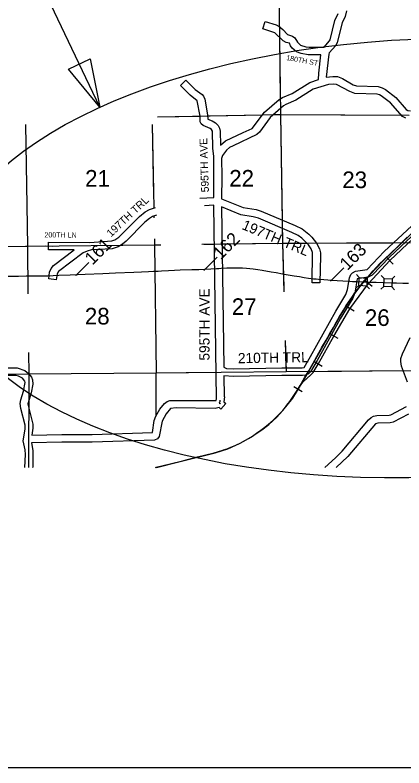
# Model space of a CAD drawing. Extents: x 10133 to 81668, y 5524 to 11018.
# Drawn here: x 14867 to 15247, y 7924 to 8660 of the extents above; entities that cross this region are included whole.
import ezdxf

# ---------------------------------------------------------------- set-up
doc = ezdxf.new("R2010")
doc.units = 0
for name, color, linetype in [('Default', 7, 'Continuous'), ('DisCLMLSUR', 7, 'Continuous'), ('dsnShtPortLev01', 7, 'Continuous'), ('DsnShtRevisedText', 7, 'Continuous'), ('dsnTextFinalPlan', 7, 'Continuous'), ('Level 3', 7, 'Continuous')]:
    doc.layers.add(name, color=color, linetype=linetype)

msp = doc.modelspace()

# ---------------------------------------------------------------- linework, layer by layer
at = {"layer": 'Default'}
for p, q in [((15236.21, 8416.3), (15229.82, 8423.16)), ((15203.2, 8403.09), (15200.58, 8405.99)), ((15215.76, 8394.4), (15208.49, 8400.33)), ((15211.01, 8402.68), (15213.92, 8405.29)), ((15227.32, 8402.23), (15224.66, 8405.09)), ((15235.14, 8401.94), (15238.01, 8404.61)), ((15202.79, 8395.27), (15199.88, 8392.65)), ((15210.61, 8394.86), (15213.22, 8391.95)), ((15227.04, 8394.41), (15224.17, 8391.74)), ((15234.86, 8394.12), (15237.52, 8391.26)), ((15198.05, 8370.2), (15190.06, 8375.11)), ((15182.49, 8343.5), (15174.33, 8348.13)), ((15167, 8316.25), (15158.9, 8320.96)), ((15147.27, 8291.53), (15139.2, 8296.3))]:
    msp.add_line(p, q, dxfattribs=at)
for points in [[(15124.6, 8686.39), (15125.11, 8648.26)], [(15124.6, 8686.39), (15126.27, 8562.47)], [(15047.66, 8480.66), (15061.22, 8481.33), (15061.34, 8521.33), (15060.35, 8529.66), (15059.91, 8545.99), (15059.01, 8547.76), (15057.59, 8548.81), (15050.73, 8551.6), (15048.69, 8553.24), (15047.91, 8555.18), (15047.71, 8560.86), (15044.94, 8575.85), (15038.03, 8581.31), (15028.7, 8590.62), (15033.91, 8596.02), (15042.99, 8586.95), (15049.69, 8581.94), (15051.07, 8580.24), (15052.35, 8577.32), (15055.11, 8562.07), (15055.34, 8557.94), (15059.7, 8556.22), (15062.96, 8554.22), (15065.45, 8551.71), (15066.79, 8549.13), (15067.47, 8546.1), (15067.78, 8532.38), (15072.67, 8536.58), (15089.67, 8544.94), (15098.61, 8548.64), (15110.72, 8564.75), (15124.99, 8577.1), (15128.26, 8579.1), (15137.64, 8582.95), (15154.77, 8593.75), (15163.51, 8596.76), (15163.58, 8602.82), (15165.55, 8620.85), (15153.29, 8620.63), (15146.34, 8621.92), (15141.99, 8623.59), (15137.74, 8627.29), (15136.17, 8629.42), (15135.03, 8632.06), (15131.88, 8632.92), (15128.8, 8634.48), (15120.77, 8642.16), (15109.1, 8645.98), (15111.22, 8653.17), (15121.95, 8649.98), (15125.02, 8648.33), (15128.58, 8645.43), (15133.16, 8640.58), (15137.98, 8639), (15140.37, 8637.48), (15142.76, 8633.05), (15145.72, 8630.11), (15150.83, 8628.5), (15154.11, 8628.08), (15168.79, 8628.15), (15174.08, 8634.25), (15174.66, 8635.51), (15179.26, 8654.2), (15182.39, 8660.98)], [(15190.61, 8663.67), (15189.4, 8658.29), (15186.45, 8652.05), (15181.61, 8632.68), (15180.21, 8629.91), (15173.88, 8622.58), (15173.31, 8621.36), (15170.97, 8598.84), (15177.42, 8599.68), (15181.87, 8599.43), (15186.78, 8597.53), (15197.33, 8591.55), (15200.53, 8590.35), (15221.49, 8589.64), (15225.55, 8588.59), (15228.75, 8586.98), (15238.89, 8579.14), (15249.07, 8567.34), (15250.56, 8566.19), (15253.22, 8565.92)], [(15125.25, 8637.95), (15126.06, 8577.75)], [(15248.46, 8558.98), (15245.39, 8560.55), (15233.73, 8573.68), (15224.46, 8580.82), (15222.74, 8581.63), (15220.75, 8582.17), (15198.92, 8583.02), (15194, 8584.83), (15180.97, 8591.88), (15177.77, 8592.19), (15172.96, 8591.6), (15158.12, 8587.04), (15141.34, 8576.43), (15131.55, 8572.36), (15129.1, 8570.83), (15116.23, 8559.65), (15105.68, 8545.18), (15103.25, 8542.73), (15080.07, 8531.97), (15076.43, 8530.08), (15073.52, 8527.55), (15069.63, 8522.33), (15068.64, 8519.52), (15069.04, 8501.99), (15068.71, 8480.14), (15089.9, 8471.43), (15102.47, 8469.5), (15107.51, 8468.01), (15140.44, 8454.13), (15147.25, 8450.58), (15154.02, 8445.38), (15156.83, 8442.61), (15161.44, 8436.78), (15164.35, 8431.09), (15165.32, 8427.28), (15165.39, 8424.34), (15164.66, 8397.84), (15157.17, 8398.12), (15157.64, 8427.45), (15156.21, 8431.09), (15153.45, 8434.98), (15147.1, 8441.48), (15143.37, 8444.16), (15137.45, 8447.26), (15104.75, 8461.03), (15099.43, 8462.44), (15087.68, 8464.26), (15068.8, 8472.07), (15070.95, 8315.62), (15073.6, 8314.31), (15080.43, 8314.09), (15127.59, 8314.99)], [(15006.1, 8560.14), (15126.27, 8562.47)], [(15055.17, 8561.09), (15108.66, 8562.13)], [(15119.24, 8562.33), (15126.27, 8562.47)], [(15126.19, 8568.37), (15126.27, 8562.47)], [(15126.27, 8562.47), (15127.79, 8459.47)], [(15126.27, 8562.47), (15244.06, 8561.79)], [(15126.27, 8562.47), (15251.87, 8561.74)], [(15126.27, 8562.47), (15128.13, 8436.72)], [(15006.1, 8560.14), (15047.7, 8560.94)], [(14877.47, 8552.72), (14879.25, 8433.82)], [(14877.47, 8552.72), (14879.25, 8433.82)], [(15000.92, 8552.72), (15002.56, 8471.1)], [(15000.92, 8552.72), (15002.32, 8483.36)], [(14860.23, 8314.95), (14869.12, 8315.01), (14876.77, 8312.26), (14880.29, 8309.48), (14883.1, 8305.81), (14884.26, 8303.24), (14884.57, 8299.02), (14882.84, 8290.36), (14879.73, 8279.77), (14880.14, 8276.68), (14884.4, 8260.03), (14884.56, 8255.86), (14883.48, 8249.18), (14912.77, 8249.84), (14942.26, 8249.66), (15001.18, 8251.65), (15002.92, 8263.54), (15004.54, 8267.84), (15008.5, 8274.56), (15012.95, 8280.01), (15015.56, 8281.93), (15018.23, 8282.9), (15020.74, 8283.17), (15063.5, 8283.04), (15063.9, 8284.58), (15061.29, 8473.83), (15052.06, 8473.23)], [(15005.14, 8463.93), (15001.33, 8462.64), (14998.25, 8460.95), (14993.73, 8457.37), (14975.6, 8438.75), (14972.08, 8435.73), (14967.93, 8433.27), (14961.81, 8431.23), (14941.84, 8430.17), (14937.45, 8429.05), (14933.49, 8427.19), (14909.47, 8409.17), (14908.27, 8406.88), (14907.39, 8400.86), (14899.97, 8401.94), (14900.91, 8408.38), (14902.31, 8412.06), (14904.55, 8414.85), (14924.94, 8430.26), (14899.75, 8430.22), (14899.79, 8437.71), (14940.12, 8437.48), (14961.64, 8438.87), (14964.47, 8439.92), (14968.47, 8442.44), (14988.67, 8462.9), (14994.14, 8467.22), (14998.24, 8469.48), (15004.23, 8471.51)], [(15002.72, 8463.16), (15002.76, 8461.48)], [(15005.18, 8217.55), (15026.86, 8223), (15062.64, 8231.92), (15074.79, 8235.92), (15086.88, 8241.21), (15097.24, 8247.05), (15107.94, 8254.21), (15114.85, 8259.61), (15122.73, 8266.69), (15128.59, 8273.25), (15138.37, 8285.43), (15148.35, 8301.97), (15183.72, 8364.44), (15190.28, 8374.88), (15196.95, 8384.94), (15203.97, 8394.34), (15210.49, 8402.42), (15218.89, 8411.8), (15226.84, 8419.94), (15260.86, 8452.53)], [(15127.59, 8314.99), (15147.55, 8314.83), (15149.39, 8315.36), (15155.7, 8325.94), (15180.16, 8370.31), (15190.12, 8386.43), (15191.73, 8391.4), (15193.5, 8402.93), (15194.79, 8406.15), (15196.5, 8407.86), (15199.5, 8409.36), (15210.86, 8411.15), (15227.34, 8428.44), (15254.52, 8453.71)], [(15259.76, 8448.34), (15232.58, 8423.07), (15215.62, 8405.35), (15211.97, 8403.65), (15200.94, 8401.78), (15198.73, 8388.32), (15196.81, 8383.04), (15184.54, 8362.85), (15162.18, 8322.17), (15155.53, 8311.03), (15153.67, 8309.12), (15150.59, 8307.69), (15147.87, 8307.34), (15127.65, 8307.49), (15080.46, 8306.59), (15070.95, 8307.24), (15071.34, 8286.52), (15071.74, 8286.46), (15071.09, 8281.86), (15072.99, 8280.22), (15068.09, 8274.55), (15066.33, 8276.06), (15062.64, 8275.33), (15024.26, 8275.7), (15018.99, 8275.24), (15014.52, 8270.1), (15010.6, 8262.95), (15007.85, 8247.87), (15006.09, 8245.71), (15003.24, 8244.38), (14942.35, 8242.16), (14912.88, 8242.35), (14883.06, 8241.67), (14884.61, 8234.19), (14884.35, 8217.84), (14884.27, 8217.55)], [(15127.91, 8451.28), (15128.13, 8436.72)], [(15003.17, 8441.03), (15003.29, 8435.14)], [(15004.21, 8217.55), (15004.87, 8217.72), (15018.6, 8221.19), (15031.93, 8224.43), (15045.3, 8227.81), (15061.56, 8231.9), (15065.59, 8233.02), (15069.12, 8234.2), (15070.77, 8234.78), (15074.04, 8235.93), (15077.84, 8237.47), (15081.9, 8239.15), (15086.75, 8241.47), (15090.49, 8243.34), (15094.95, 8245.73), (15098.91, 8248.19), (15102.91, 8250.94), (15107.04, 8253.89), (15111.03, 8256.91), (15114.57, 8259.79), (15119, 8263.69), (15122.31, 8266.93), (15124.67, 8269.46), (15127.42, 8272.31), (15130.04, 8275.35), (15132.53, 8278.43), (15135.32, 8282.01), (15138.03, 8285.81), (15139.41, 8287.92), (15140.07, 8288.92), (15142.49, 8292.66), (15145.47, 8297.7), (15149.67, 8305.04), (15153.76, 8312.15), (15159.79, 8322.51), (15163.76, 8329.65), (15165.31, 8332.52), (15166.38, 8334.5), (15170.8, 8342.04), (15174.41, 8348.39), (15177.88, 8354.36), (15180.99, 8359.76), (15183.55, 8364.29), (15186.2, 8368.81), (15187.65, 8371.23), (15190.46, 8375.82), (15192.63, 8378.93), (15195.84, 8383.65), (15198.95, 8388.07), (15201.41, 8391.45), (15203.93, 8394.66), (15206.75, 8398.2), (15210.22, 8402.46), (15214.35, 8407.18), (15216.68, 8409.83), (15219.79, 8413.11), (15223.62, 8417.04), (15226.02, 8419.43), (15228.6, 8422.05), (15232.93, 8426.09), (15241.61, 8434.47), (15249.97, 8442.47)], [(15128.13, 8436.72), (15253.02, 8437.25)], [(15136, 8282.96), (15138.03, 8285.81), (15139.41, 8287.92), (15140.07, 8288.92), (15142.49, 8292.66), (15145.47, 8297.7), (15148.44, 8301.19), (15155.95, 8308.01), (15158.17, 8310.43), (15162.95, 8318.61), (15178.39, 8345.84), (15194.05, 8372.68), (15212.12, 8397.39), (15233, 8419.74), (15255.62, 8441.36)], [(15161.38, 8436.86), (15236.57, 8437.18)], [(14753.71, 8432.47), (14879.25, 8433.82)], [(14810.27, 8433.07), (14879.25, 8433.82)], [(14877.2, 8433.8), (14897.09, 8433.98), (14903.52, 8433.94)], [(14879.25, 8433.82), (15003.29, 8435.14)], [(14879.25, 8433.82), (14899.77, 8434.04)], [(14879.25, 8433.82), (14879.74, 8387.27)], [(14970.49, 8434.79), (15003.29, 8435.14)], [(15003.29, 8435.14), (15009.49, 8435.22)], [(15003.29, 8435.14), (15007.46, 8435.19)], [(15003.29, 8435.14), (15004.86, 8310.09)], [(15003.29, 8435.14), (15004.86, 8310.09)], [(15049.5, 8435.72), (15128.13, 8436.72)], [(15051.41, 8435.75), (15061.77, 8435.88)], [(15069.34, 8435.97), (15128.13, 8436.72)], [(15128.13, 8436.72), (15151.91, 8436.82)], [(15128.13, 8436.72), (15129.35, 8393.75)], [(15128.13, 8436.72), (15129.48, 8389.33)], [(15130.83, 8341.72), (15131.7, 8311.2)], [(15130.84, 8341.52), (15131.59, 8314.96)], [(15250.07, 8301.04), (15244.31, 8316.62), (15243.65, 8321.22), (15243.82, 8324.16), (15245.29, 8328.76), (15252.94, 8344.53)], [(14880.33, 8330.05), (14880.54, 8308.98)], [(15131.7, 8311.2), (15253.94, 8312.44)], [(15155.78, 8311.45), (15245.79, 8312.36)], [(14755.55, 8307.63), (14880.54, 8308.98)], [(14876.66, 8217.55), (14876.74, 8217.7), (14877.21, 8230.24), (14877.05, 8234.9), (14875.12, 8243.72), (14876.93, 8255.03), (14876.96, 8259.03), (14872.81, 8275.07), (14872.22, 8279.92), (14872.78, 8283.63), (14875.55, 8292.11), (14877.15, 8300.5), (14876.72, 8301.84), (14874.27, 8304.98), (14870.63, 8306.77), (14868.09, 8307.58), (14859.74, 8307.4)], [(14880.54, 8308.98), (14880.37, 8217.55)], [(14880.54, 8308.98), (15004.86, 8310.09)], [(14880.67, 8308.98), (15004.86, 8310.09)], [(15004.75, 8268.18), (15004.86, 8310.09)], [(15004.86, 8310.09), (15131.7, 8311.2)], [(15004.86, 8310.09), (15063.41, 8310.61)], [(14880.49, 8283.02), (14880.48, 8275.47)], [(15066.28, 8280.51), (15066.61, 8280.81), (15067.39, 8282.41), (15067.51, 8283.27), (15067.51, 8283.27)], [(15067.51, 8283.27), (15067.51, 8283.27)], [(15066.28, 8280.51), (15067, 8280.24), (15067.49, 8280.02), (15067.71, 8279.83)], [(15169.68, 8217.55), (15180, 8226.9), (15186.53, 8233.52), (15212.09, 8264.01), (15214.74, 8266.35), (15217.17, 8267.69), (15220.21, 8268.44), (15232.45, 8268.77), (15234.11, 8269.16), (15249.18, 8277.21)], [(15251.07, 8269.65), (15236.25, 8261.97), (15233.17, 8261.29), (15221.24, 8261.01), (15219.13, 8260.26), (15191.95, 8228.34), (15180.67, 8217.55)]]:
    msp.add_lwpolyline(points, dxfattribs=at)
for points in [[(15203.2, 8403.09), (15211.01, 8402.68), (15210.61, 8394.86), (15202.79, 8395.27)], [(15227.32, 8402.23), (15235.14, 8401.94), (15234.86, 8394.12), (15227.04, 8394.41)]]:
    msp.add_lwpolyline(points, close=True, dxfattribs=at)
at = {"layer": 'DisCLMLSUR'}
msp.add_line((14949.85, 8569.5), (14513.59, 9488.76), dxfattribs=at)
at = {"layer": 'dsnShtPortLev01'}
msp.add_lwpolyline([(14940.34, 8616.87), (14949.85, 8569.5), (14919.17, 8606.82)], close=True, dxfattribs=at)
at = {"layer": 'DsnShtRevisedText'}
msp.add_lwpolyline([(14858.17, 8404.64), (14870.41, 8404.64), (14877.93, 8404.73), (14878.45, 8404.74), (14886.87, 8404.77), (14899.26, 8404.92), (14904.22, 8405.11), (14909.8, 8405.32), (14920.84, 8405.78), (14935.63, 8406.43), (14952.93, 8407.08), (14965.2, 8407.69), (14983.17, 8408.46), (14990.63, 8408.74), (14997.35, 8409.17), (15002.43, 8409.45), (15006.78, 8409.51), (15010.14, 8409.61), (15016.8, 8410.01), (15022.81, 8410.38), (15028.42, 8410.71), (15039.58, 8410.96), (15043.03, 8410.96), (15046.67, 8411.02), (15051.94, 8411.24), (15058.41, 8411.61), (15063.72, 8411.89), (15065.94, 8412.02), (15068.28, 8412.16), (15073.98, 8412.5), (15084.99, 8412.63), (15089.01, 8412.64), (15093.22, 8412.29), (15099.63, 8411.54), (15104.07, 8411.06), (15108.48, 8410.35), (15117.17, 8408.74), (15121.95, 8407.91), (15128.27, 8406.79), (15131.84, 8406.18), (15139.52, 8404.89), (15144.94, 8404.06), (15149.38, 8403.32), (15153.73, 8402.67), (15158.6, 8401.96), (15161.07, 8401.95), (15163.19, 8401.53), (15168.62, 8401.19), (15176.23, 8400.51), (15181.66, 8400.11), (15186.96, 8399.9), (15193.99, 8399.53), (15196.67, 8399.43), (15200.12, 8399.31), (15206.38, 8399), (15211.68, 8398.72), (15219.54, 8398.51), (15227.83, 8398.29), (15235.48, 8398.01), (15239.65, 8397.9), (15245.59, 8397.74), (15251.2, 8397.52)], dxfattribs=at)
at = {"layer": 'dsnTextFinalPlan'}
msp.add_ellipse((15267.06, 8422.1), major_axis=(466.54, 18.24), ratio=0.458759, dxfattribs=at)
at = {"layer": 'Level 3'}
msp.add_lwpolyline([(13732.52, 9944.02), (16867.53, 9944.02), (16867.53, 7924.02), (13732.52, 7924.02)], close=True, dxfattribs=at)

# ---------------------------------------------------------------- texts
at = {"layer": 'Default'}
for s, height, rotation, p in [('180TH ST', 5, 349.44177, (15131.6, 8615.72)), ('595TH AVE', 7.5, 91.83771, (15056.38, 8486.56)), ('21', 16.25, 0.02322, (14935.58, 8491.93)), ('22', 16.25, 0.02406, (15076.23, 8491.99)), ('23', 16.25, 0.02472, (15186.59, 8490.5)), ('197TH TRL', 7.5, 43.50686, (14960.82, 8442.24)), ('197TH TRL', 10, 337.10586, (15087.82, 8450.73)), ('200TH LN', 5, 359.60286, (14895.83, 8442.38)), ('‒‒162', 12.5, 45, (15054.68, 8406.75)), ('‒‒161', 12.5, 45, (14929.49, 8401.55)), ('‒‒163', 12.5, 45, (15178.37, 8396.29)), ('595TH AVE', 10, 90, (15056.98, 8322.01)), ('27', 16.25, 0.02407, (15078.73, 8366.57)), ('28', 16.25, 0.02321, (14935.3, 8357.28)), ('26', 16.25, 0.02484, (15208.63, 8355.84)), ('210TH TRL', 10, 0.83551, (15084.75, 8319.39))]:
    msp.add_text(s, height=height, rotation=rotation, dxfattribs=at).set_placement(p)

doc.saveas('drawing.dxf')
